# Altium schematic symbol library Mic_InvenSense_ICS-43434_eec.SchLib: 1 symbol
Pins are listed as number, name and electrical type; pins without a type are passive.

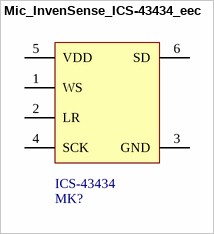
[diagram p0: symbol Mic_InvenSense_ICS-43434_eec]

## Mic_InvenSense_ICS-43434_eec
designator MK?  Part Number: ICS-43434
MIC MEMS MULTI-MODE OMNI -26DB; Manufacturer: InvenSense
footprint InvenSense_ICS-43434_0
pins: 1 WS, 2 LR, 3 GND, 4 SCK, 5 VDD, 6 SD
